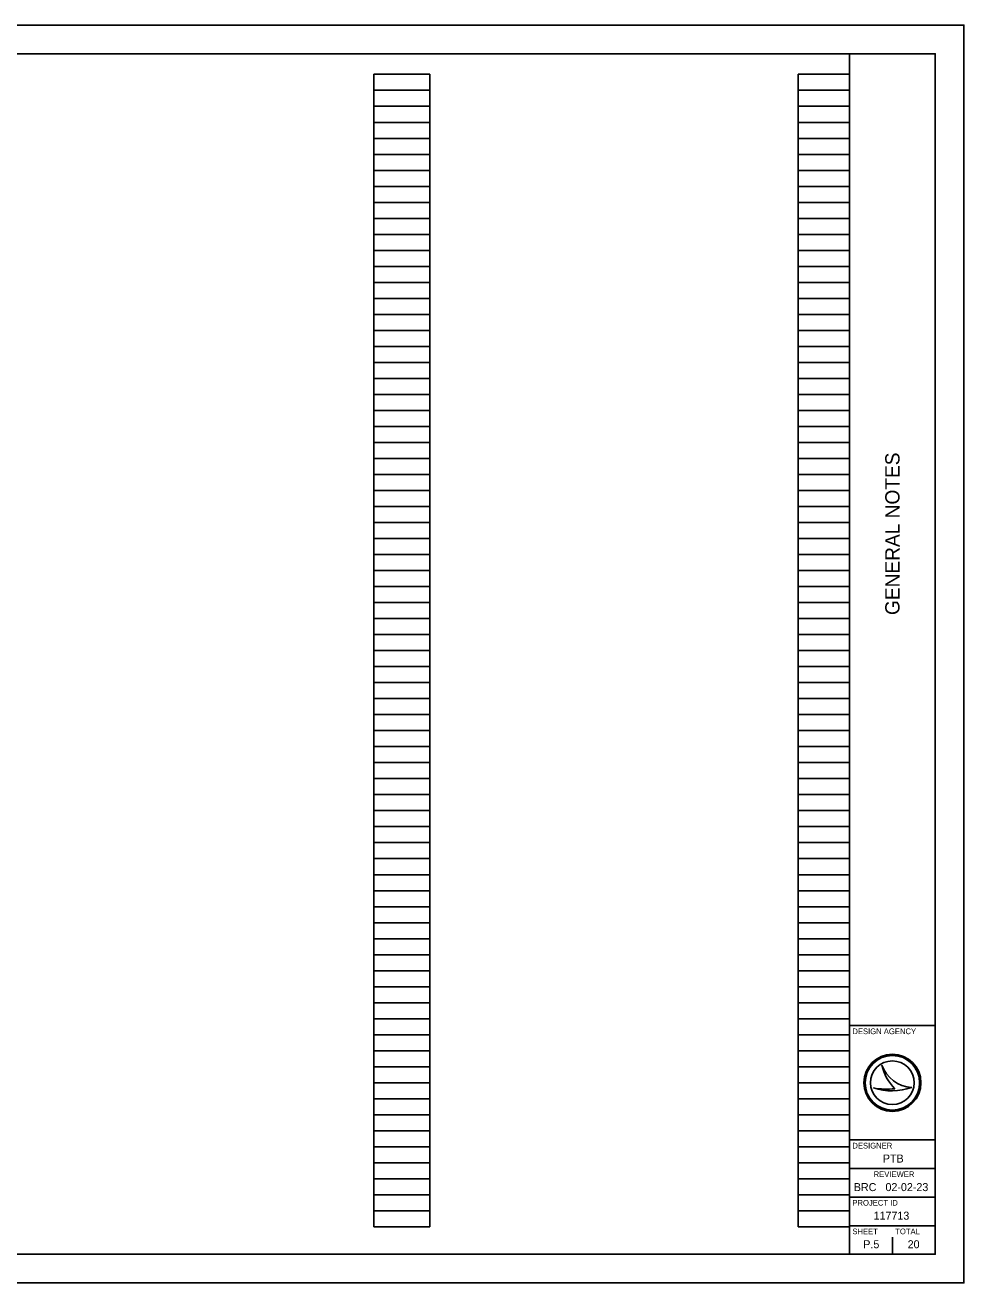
# Model space of a CAD drawing. Extents: x 0 to 34, y 0 to 22.
# Drawn here: x 17.58 to 34, y 0 to 22 of the extents above; entities that cross this region are included whole.
import ezdxf

# ---------------------------------------------------------------- set-up
doc = ezdxf.new("R2010")
doc.units = 0
for name, color, linetype in [('SH_Border', 7, 'Continuous'), ('SH_Cut_Line', 7, 'Continuous'), ('SH_Data', 7, 'Continuous')]:
    doc.layers.add(name, color=color, linetype=linetype)

msp = doc.modelspace()

# ---------------------------------------------------------------- linework, layer by layer
at = {"layer": 'SH_Border'}
for p, q in [((32, 0.5), (32, 21.5)), ((32, 4.5), (33.5, 4.5)), ((32, 2.5), (33.5, 2.5)), ((32, 2), (33.5, 2)), ((32, 1.5), (33.5, 1.5)), ((32, 1), (33.5, 1))]:
    msp.add_line(p, q, dxfattribs=at)
msp.add_lwpolyline([(1.5, 21.5), (33.5, 21.5), (33.5, 0.5), (1.5, 0.5)], close=True, dxfattribs=at)
at = {"layer": 'SH_Cut_Line'}
msp.add_lwpolyline([(0, 0), (34, 0), (34, 22), (0, 22)], close=True, dxfattribs=at)
at = {"layer": 'SH_Data'}
for p, q in [((23.68, 0.98), (23.68, 21.14)), ((23.68, 21.14), (24.66, 21.14)), ((24.66, 0.98), (24.66, 21.14)), ((31.1, 0.98), (31.1, 21.14)), ((31.1, 21.14), (32, 21.14)), ((32, 0.98), (32, 21.14)), ((23.68, 20.86), (24.66, 20.86)), ((31.1, 20.86), (32, 20.86)), ((23.68, 20.58), (24.66, 20.58)), ((31.1, 20.58), (32, 20.58)), ((23.68, 20.3), (24.66, 20.3)), ((31.1, 20.3), (32, 20.3)), ((23.68, 20.02), (24.66, 20.02)), ((31.1, 20.02), (32, 20.02)), ((23.68, 19.74), (24.66, 19.74)), ((31.1, 19.74), (32, 19.74)), ((23.68, 19.46), (24.66, 19.46)), ((31.1, 19.46), (32, 19.46)), ((23.68, 19.18), (24.66, 19.18)), ((31.1, 19.18), (32, 19.18)), ((23.68, 18.9), (24.66, 18.9)), ((31.1, 18.9), (32, 18.9)), ((23.68, 18.62), (24.66, 18.62)), ((31.1, 18.62), (32, 18.62)), ((23.68, 18.34), (24.66, 18.34)), ((31.1, 18.34), (32, 18.34)), ((23.68, 18.06), (24.66, 18.06)), ((31.1, 18.06), (32, 18.06)), ((23.68, 17.78), (24.66, 17.78)), ((31.1, 17.78), (32, 17.78)), ((23.68, 17.5), (24.66, 17.5)), ((31.1, 17.5), (32, 17.5)), ((23.68, 17.22), (24.66, 17.22)), ((31.1, 17.22), (32, 17.22)), ((23.68, 16.94), (24.66, 16.94)), ((31.1, 16.94), (32, 16.94)), ((23.68, 16.66), (24.66, 16.66)), ((31.1, 16.66), (32, 16.66)), ((23.68, 16.38), (24.66, 16.38)), ((31.1, 16.38), (32, 16.38)), ((23.68, 16.1), (24.66, 16.1)), ((31.1, 16.1), (32, 16.1)), ((23.68, 15.82), (24.66, 15.82)), ((31.1, 15.82), (32, 15.82)), ((23.68, 15.54), (24.66, 15.54)), ((31.1, 15.54), (32, 15.54)), ((23.68, 15.26), (24.66, 15.26)), ((31.1, 15.26), (32, 15.26)), ((23.68, 14.98), (24.66, 14.98)), ((31.1, 14.98), (32, 14.98)), ((23.68, 14.7), (24.66, 14.7)), ((31.1, 14.7), (32, 14.7)), ((23.68, 14.42), (24.66, 14.42)), ((31.1, 14.42), (32, 14.42)), ((23.68, 14.14), (24.66, 14.14)), ((31.1, 14.14), (32, 14.14)), ((23.68, 13.86), (24.66, 13.86)), ((31.1, 13.86), (32, 13.86)), ((23.68, 13.58), (24.66, 13.58)), ((31.1, 13.58), (32, 13.58)), ((23.68, 13.3), (24.66, 13.3)), ((31.1, 13.3), (32, 13.3)), ((23.68, 13.02), (24.66, 13.02)), ((31.1, 13.02), (32, 13.02)), ((23.68, 12.74), (24.66, 12.74)), ((31.1, 12.74), (32, 12.74)), ((23.68, 12.46), (24.66, 12.46)), ((31.1, 12.46), (32, 12.46)), ((23.68, 12.18), (24.66, 12.18)), ((31.1, 12.18), (32, 12.18)), ((23.68, 11.9), (24.66, 11.9)), ((31.1, 11.9), (32, 11.9)), ((23.68, 11.62), (24.66, 11.62)), ((31.1, 11.62), (32, 11.62)), ((23.68, 11.34), (24.66, 11.34)), ((31.1, 11.34), (32, 11.34)), ((23.68, 11.06), (24.66, 11.06)), ((31.1, 11.06), (32, 11.06)), ((23.68, 10.78), (24.66, 10.78)), ((31.1, 10.78), (32, 10.78)), ((23.68, 10.5), (24.66, 10.5)), ((31.1, 10.5), (32, 10.5)), ((23.68, 10.22), (24.66, 10.22)), ((31.1, 10.22), (32, 10.22)), ((23.68, 9.94), (24.66, 9.94)), ((31.1, 9.94), (32, 9.94)), ((23.68, 9.66), (24.66, 9.66)), ((31.1, 9.66), (32, 9.66)), ((23.68, 9.38), (24.66, 9.38)), ((31.1, 9.38), (32, 9.38)), ((23.68, 9.1), (24.66, 9.1)), ((31.1, 9.1), (32, 9.1)), ((23.68, 8.82), (24.66, 8.82)), ((31.1, 8.82), (32, 8.82)), ((23.68, 8.54), (24.66, 8.54)), ((31.1, 8.54), (32, 8.54)), ((23.68, 8.26), (24.66, 8.26)), ((31.1, 8.26), (32, 8.26)), ((23.68, 7.98), (24.66, 7.98)), ((31.1, 7.98), (32, 7.98)), ((23.68, 7.7), (24.66, 7.7)), ((31.1, 7.7), (32, 7.7)), ((23.68, 7.42), (24.66, 7.42)), ((31.1, 7.42), (32, 7.42)), ((23.68, 7.14), (24.66, 7.14)), ((31.1, 7.14), (32, 7.14)), ((23.68, 6.86), (24.66, 6.86)), ((31.1, 6.86), (32, 6.86)), ((23.68, 6.58), (24.66, 6.58)), ((31.1, 6.58), (32, 6.58)), ((23.68, 6.3), (24.66, 6.3)), ((31.1, 6.3), (32, 6.3)), ((23.68, 6.02), (24.66, 6.02)), ((31.1, 6.02), (32, 6.02)), ((23.68, 5.74), (24.66, 5.74)), ((31.1, 5.74), (32, 5.74)), ((23.68, 5.46), (24.66, 5.46)), ((31.1, 5.46), (32, 5.46)), ((23.68, 5.18), (24.66, 5.18)), ((31.1, 5.18), (32, 5.18)), ((23.68, 4.9), (24.66, 4.9)), ((31.1, 4.9), (32, 4.9)), ((23.68, 4.62), (24.66, 4.62)), ((31.1, 4.62), (32, 4.62)), ((23.68, 4.34), (24.66, 4.34)), ((31.1, 4.34), (32, 4.34)), ((23.68, 4.06), (24.66, 4.06)), ((31.1, 4.06), (32, 4.06)), ((23.68, 3.78), (24.66, 3.78)), ((31.1, 3.78), (32, 3.78)), ((32.567, 3.81), (32.567, 3.81)), ((23.68, 3.5), (24.66, 3.5)), ((31.1, 3.5), (32, 3.5)), ((32.417, 3.41), (32.417, 3.41)), ((32.75, 3.5), (32.75, 3.5)), ((33.087, 3.419), (33.087, 3.419)), ((23.68, 3.22), (24.66, 3.22)), ((31.1, 3.22), (32, 3.22)), ((23.68, 2.94), (24.66, 2.94)), ((31.1, 2.94), (32, 2.94)), ((23.68, 2.66), (24.66, 2.66)), ((31.1, 2.66), (32, 2.66)), ((23.68, 2.38), (24.66, 2.38)), ((31.1, 2.38), (32, 2.38)), ((23.68, 2.1), (24.66, 2.1)), ((31.1, 2.1), (32, 2.1)), ((23.68, 1.82), (24.66, 1.82)), ((31.1, 1.82), (32, 1.82)), ((23.68, 1.54), (24.66, 1.54)), ((31.1, 1.54), (32, 1.54)), ((23.68, 1.26), (24.66, 1.26)), ((31.1, 1.26), (32, 1.26)), ((23.68, 0.98), (24.66, 0.98)), ((31.1, 0.98), (32, 0.98)), ((32.375, 0.675), (32.375, 0.675)), ((32.75, 0.5), (32.75, 0.8))]:
    msp.add_line(p, q, dxfattribs=at)
for radius in [0.5, 0.477, 0.477, 0.382]:
    msp.add_circle((32.75, 3.5), radius, dxfattribs=at)
for centre, radius, start, end in [((33.116, 3.998), 0.58, 198.9257, 198.9319), ((33.347, 3.97), 0.796, 191.6379, 191.6421), ((33.116, 3.998), 0.58, 198.9319, 267.1657), ((33.347, 3.97), 0.796, 191.6421, 226.0947), ((32.739, 4.37), 1.013, 251.4576, 290.0832), ((32.648, 4.654), 1.266, 259.4964, 259.4995), ((32.739, 4.37), 1.013, 251.4527, 251.4576), ((32.648, 4.654), 1.266, 259.4995, 276.6672)]:
    msp.add_arc(centre, radius, start, end, dxfattribs=at)

# ---------------------------------------------------------------- texts
msp.add_text('GENERAL NOTES', height=0.25, rotation=90, dxfattribs=at).set_placement((32.875, 11.682))
for s, height, p in [('DESIGN AGENCY', 0.1, (32.05, 4.35)), ('DESIGNER', 0.1, (32.05, 2.35)), ('PTB', 0.14, (32.584, 2.105)), ('REVIEWER', 0.1, (32.422, 1.85)), ('BRC', 0.14, (32.075, 1.605)), ('02-02-23', 0.14, (32.629, 1.605)), ('PROJECT ID', 0.1, (32.05, 1.35)), ('117713', 0.14, (32.421, 1.105)), ('SHEET', 0.1, (32.05, 0.85)), ('TOTAL', 0.1, (32.8, 0.85)), ('P.5', 0.14, (32.241, 0.605)), ('20', 0.14, (33.017, 0.605))]:
    msp.add_text(s, height=height, dxfattribs=at).set_placement(p)

doc.saveas('drawing.dxf')
